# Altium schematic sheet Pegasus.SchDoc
size Tabloid; SheetNumber: 2; SheetTotal: 3
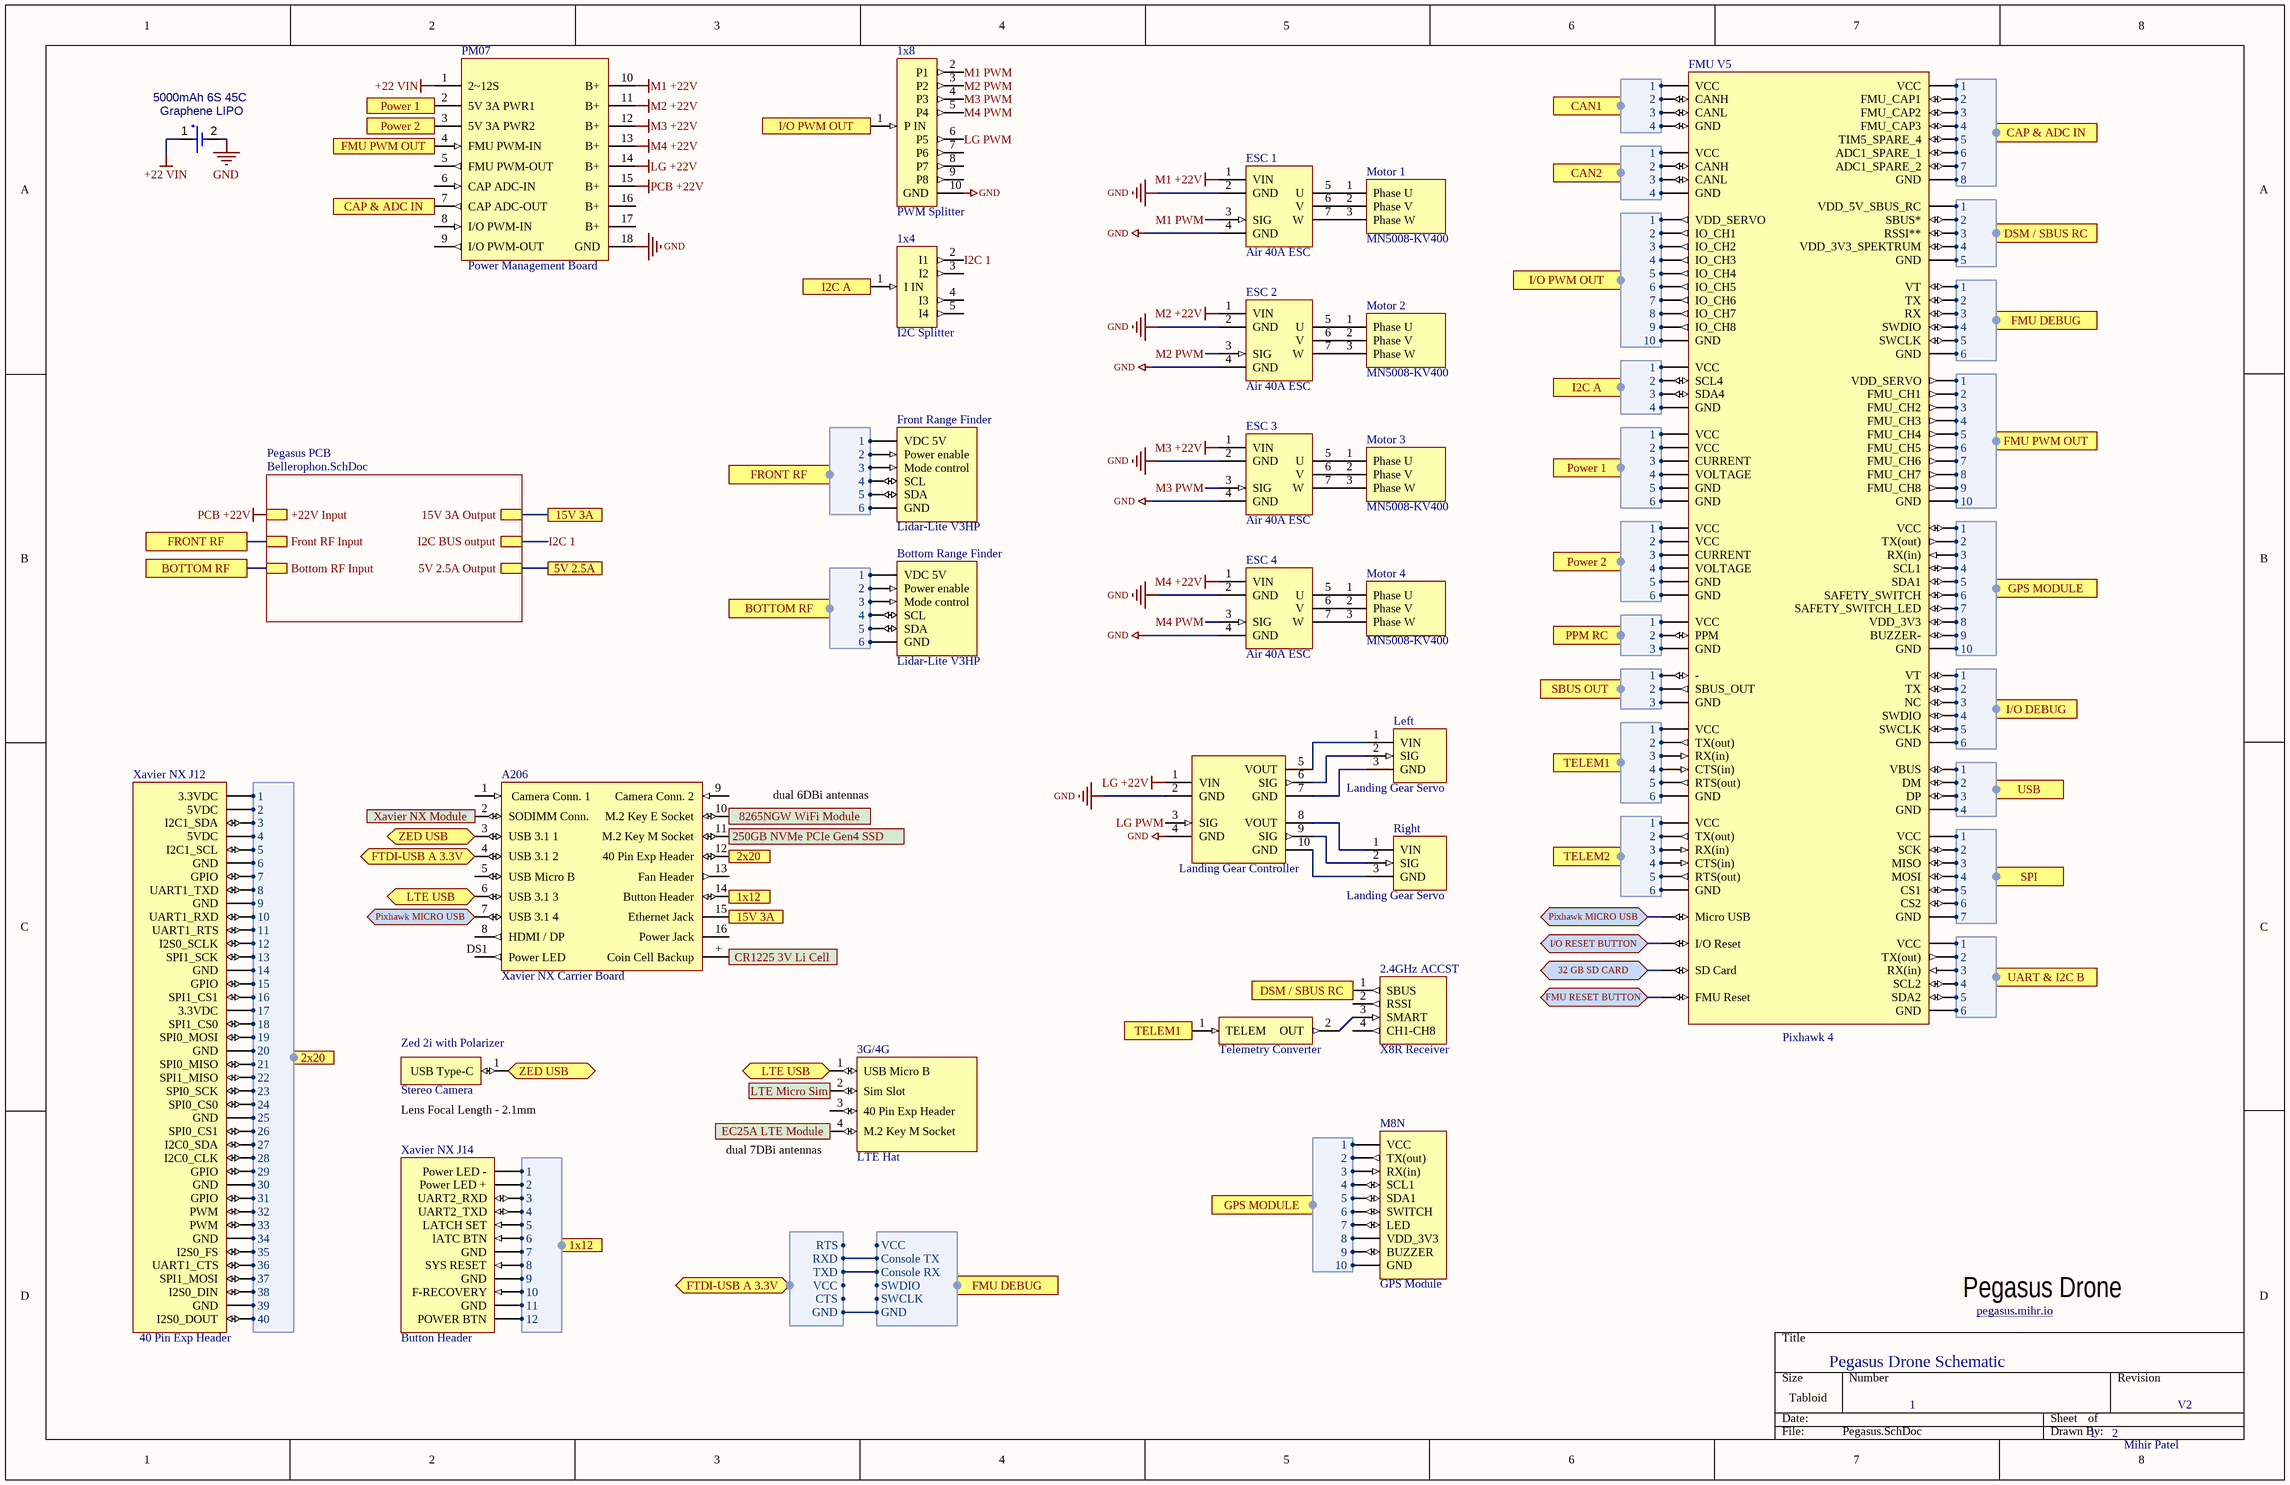
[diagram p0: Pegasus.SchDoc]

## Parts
1x4  I2C Splitter
1x8  PWM Splitter
2.4GHz_ACCST  X8R Receiver
3G/4G  LTE Hat
5000mAh_6S_45C  Graphene LIPO  [SEIK-MS621FE-FL11E-2_V]
A206  Xavier NX Carrier Board
Bottom_Range_Finder  Lidar-Lite V3HP
ESC_1  Air 40A ESC
ESC_2  Air 40A ESC
ESC_3  Air 40A ESC
ESC_4  Air 40A ESC
FMU_V5  Pixhawk 4
Front_Range_Finder  Lidar-Lite V3HP
Left  Landing Gear Servo
LGC  Landing Gear Controller
M8N  GPS Module
Motor_1  MN5008-KV400
Motor_2  MN5008-KV400
Motor_3  MN5008-KV400
Motor_4  MN5008-KV400
PM07  Power Management Board
Right  Landing Gear Servo
TC1  Telemetry Converter
Xavier_NX_J12  40 Pin Exp Header
Xavier_NX_J14  Button Header
Zed_2i_with_Polarizer  Stereo Camera

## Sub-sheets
Pegasus PCB = Bellerophon.SchDoc: 15V 3A Output, +22V Input, Front RF Input, Bottom RF Input, I2C BUS output, 5V 2.5A Output

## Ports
1x12 (harness 1x12), 1x12 (harness *), 2x20 (harness NX), 5V 2.5A, 15V 3A, 32 GB SD CARD (bidir), 250GB NVMe PCIe Gen4 SSD, 8265NGW WiFi Module, BOTTOM RF (harness L2), CAN1 (harness CAN1), CAN2 (harness CAN2), CAP & ADC IN (harness CAP & ADC IN), CR1225 3V Li Cell, DSM / SBUS RC (harness DSM / SBUS RC), EC25A LTE Module, FMU DEBUG (harness FDD), FMU DEBUG (harness FMU DEBUG), FMU PWM OUT (harness FMU PWM OUT), FMU RESET BUTTON (bidir), FRONT RF (harness L1), FTDI-USB A 3.3V (bidir, harness USBD), GPS MODULE (harness GPS MODULE), GPS MODULE (harness GPS), I2C A (harness I2C A), I/O DEBUG (harness IO DEBUG), I/O PWM OUT (harness I/O PWM OUT), I/O RESET BUTTON (bidir), LTE Micro Sim, LTE USB (bidir), Pixhawk MICRO USB (bidir), Power 1 (harness Power 1), Power 2 (harness Power 2), PPM RC (harness PPM RC), SBUS OUT (harness SBUS OUT), SPI (harness SPI), TELEM1 (harness TELEM1), TELEM2 (harness TELEM2), UART & I2C B (harness UART & I2C B), USB (harness USB), Xavier NX Module, ZED USB (bidir)

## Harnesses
CAP & ADC IN: 1, 2, 3, 4, 5, 6, 7, 8
DSM / SBUS RC: 1, 2, 3, 4, 5
FMU DEBUG: 1, 2, 3, 4, 5, 6
FMU PWM OUT: 1, 2, 3, 4, 5, 6, 7, 8, 9, 10
IO DEBUG: 1, 2, 3, 4, 5, 6
SPI: 1, 2, 3, 4, 5, 6, 7
CAN1: 1, 2, 3, 4
CAN2: 1, 2, 3, 4
I/O PWM OUT: 1, 2, 3, 4, 5, 6, 7, 8, 9, 10
I2C A: 1, 2, 3, 4
Power 1: 1, 2, 3, 4, 5, 6
Power 2: 1, 2, 3, 4, 5, 6
SBUS OUT: 1, 2, 3
TELEM1: 1, 2, 3, 4, 5, 6
TELEM2: 1, 2, 3, 4, 5, 6
GPS MODULE: 1, 2, 3, 4, 5, 6, 7, 8, 9, 10
PPM RC: 1, 2, 3
USB: 1, 2, 3, 4
UART & I2C B: 1, 2, 3, 4, 5, 6
L1: 1, 2, 3, 4, 5, 6
L2: 1, 2, 3, 4, 5, 6
GPS: 1, 2, 3, 4, 5, 6, 7, 8, 9, 10
NX: 1, 2, 3, 4, 5, 6, 7, 8, 9, 10, 11, 12, 13, 14, 15, 16, 17, 18, 19, 20, 21, 22, 23, 24, 25, 26, 27, 28, 29, 30, 31, 32, 33, 34, 35, 36, 37, 38, 39, 40
1x12: 1, 2, 3, 4, 5, 6, 7, 8, 9, 10, 11, 12
FDD: VCC, Console TX, Console RX, SWDIO, SWCLK, GND
USBD: GND, CTS, VCC, TXD, RXD, RTS

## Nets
+22 VIN: 5000mAh_6S_45C.1(+) PM07.1(2~12S)
GND: 1x8.10(GND) 5000mAh_6S_45C.2(-) ESC_1.2(GND) ESC_1.4(GND) ESC_2.2(GND) ESC_2.4(GND) ESC_3.2(GND) ESC_3.4(GND) ESC_4.2(GND) ESC_4.4(GND) LGC.2(GND) LGC.4(GND) PM07.18(GND)
LG +22V: LGC.1(VIN) PM07.14(B+)
M1 +22V: ESC_1.1(VIN) PM07.10(B+)
M2 +22V: ESC_2.1(VIN) PM07.11(B+)
M3 +22V: ESC_3.1(VIN) PM07.12(B+)
M4 +22V: ESC_4.1(VIN) PM07.13(B+)
PCB +22V: PM07.15(B+) ; sheet Pegasus PCB/+22V Input
5V 2.5A: port 5V 2.5A, sheet Pegasus PCB/5V 2.5A Output
15V 3A: A206.15(Ethernet_Jack) ; port 15V 3A, sheet Pegasus PCB/15V 3A Output
32 GB SD CARD: FMU_V5.117(SD_Card) ; port 32 GB SD CARD
250GB NVMe PCIe Gen4 SSD: A206.11(M.2_Key_M_Socket) ; port 250GB NVMe PCIe Gen4 SSD
8265NGW WiFi Module: A206.10(M.2_Key_E_Socket) ; port 8265NGW WiFi Module
CR1225 3V Li Cell: A206.+(Coin_Cell_Backup) ; port CR1225 3V Li Cell
EC25A LTE Module: 3G/4G.4(M.2_Key_M_Socket) ; port EC25A LTE Module
FMU RESET BUTTON: FMU_V5.118(FMU_Reset) ; port FMU RESET BUTTON
I2C 1: 1x4.2(I1) ; sheet Pegasus PCB/I2C BUS output
I/O RESET BUTTON: FMU_V5.116(I/O_Reset) ; port I/O RESET BUTTON
LG PWM: 1x8.6(P5) LGC.3(SIG)
LTE Micro Sim: 3G/4G.2(Sim_Slot) ; port LTE Micro Sim
LTE USB: 3G/4G.1(USB_Micro_B) A206.6(USB_3.1_3) ; port LTE USB
M1 PWM: 1x8.2(P1) ESC_1.3(SIG)
M2 PWM: 1x8.3(P2) ESC_2.3(SIG)
M3 PWM: 1x8.4(P3) ESC_3.3(SIG)
M4 PWM: 1x8.5(P4) ESC_4.3(SIG)
Pixhawk MICRO USB: A206.7(USB_3.1_4) FMU_V5.115(Micro_USB) ; port Pixhawk MICRO USB
Xavier NX Module: A206.2(SODIMM_Conn.) ; port Xavier NX Module
ZED USB: A206.3(USB_3.1_1) Zed_2i_with_Polarizer.1(USB_Type-C) ; port ZED USB
Net2.4GHz_ACCST_3: 2.4GHz_ACCST.3(SMART) TC1.2(OUT)
NetBottom_Range_Finder_1: Bottom_Range_Finder.1(VDC_5V) ; port BOTTOM RF.1
NetBottom_Range_Finder_2: Bottom_Range_Finder.2(Power_enable) ; port BOTTOM RF.2
NetBottom_Range_Finder_3: Bottom_Range_Finder.3(Mode_control) ; port BOTTOM RF.3
NetBottom_Range_Finder_4: Bottom_Range_Finder.4(SCL) ; port BOTTOM RF.4
NetBottom_Range_Finder_5: Bottom_Range_Finder.5(SDA) ; port BOTTOM RF.5
NetBottom_Range_Finder_6: Bottom_Range_Finder.6(GND) ; port BOTTOM RF.6
NetESC_1_5: ESC_1.5(U) Motor_1.1(Phase_U)
NetESC_1_6: ESC_1.6(V) Motor_1.2(Phase_V)
NetESC_1_7: ESC_1.7(W) Motor_1.3(Phase_W)
NetESC_2_5: ESC_2.5(U) Motor_2.1(Phase_U)
NetESC_2_6: ESC_2.6(V) Motor_2.2(Phase_V)
NetESC_2_7: ESC_2.7(W) Motor_2.3(Phase_W)
NetESC_3_5: ESC_3.5(U) Motor_3.1(Phase_U)
NetESC_3_6: ESC_3.6(V) Motor_3.2(Phase_V)
NetESC_3_7: ESC_3.7(W) Motor_3.3(Phase_W)
NetESC_4_5: ESC_4.5(U) Motor_4.1(Phase_U)
NetESC_4_6: ESC_4.6(V) Motor_4.2(Phase_V)
NetESC_4_7: ESC_4.7(W) Motor_4.3(Phase_W)
NetFMU_V5_1: FMU_V5.1(VCC) ; port Power 1.1
NetFMU_V5_2: FMU_V5.2(VCC) ; port Power 1.2
NetFMU_V5_3: FMU_V5.3(CURRENT) ; port Power 1.3
NetFMU_V5_4: FMU_V5.4(VOLTAGE) ; port Power 1.4
NetFMU_V5_5: FMU_V5.5(GND) ; port Power 1.5
NetFMU_V5_6: FMU_V5.6(GND) ; port Power 1.6
NetFMU_V5_7: FMU_V5.7(VCC) ; port Power 2.1
NetFMU_V5_8: FMU_V5.8(VCC) ; port Power 2.2
NetFMU_V5_9: FMU_V5.9(CURRENT) ; port Power 2.3
NetFMU_V5_10: FMU_V5.10(VOLTAGE) ; port Power 2.4
NetFMU_V5_11: FMU_V5.11(GND) ; port Power 2.5
NetFMU_V5_12: FMU_V5.12(GND) ; port Power 2.6
NetFMU_V5_13: FMU_V5.13(VCC) ; port TELEM1.1
NetFMU_V5_14: FMU_V5.14(TX(out)) ; port TELEM1.2
NetFMU_V5_15: FMU_V5.15(RX(in)) ; port TELEM1.3
NetFMU_V5_16: FMU_V5.16(CTS(in)) ; port TELEM1.4
NetFMU_V5_17: FMU_V5.17(RTS(out)) ; port TELEM1.5
NetFMU_V5_18: FMU_V5.18(GND) ; port TELEM1.6
NetFMU_V5_19: FMU_V5.19(VBUS) ; port USB.1
NetFMU_V5_20: FMU_V5.20(DM) ; port USB.2
NetFMU_V5_21: FMU_V5.21(DP) ; port USB.3
NetFMU_V5_22: FMU_V5.22(GND) ; port USB.4
NetFMU_V5_23: FMU_V5.23(VCC) ; port TELEM2.1
NetFMU_V5_24: FMU_V5.24(TX(out)) ; port TELEM2.2
NetFMU_V5_25: FMU_V5.25(RX(in)) ; port TELEM2.3
NetFMU_V5_26: FMU_V5.26(CTS(in)) ; port TELEM2.4
NetFMU_V5_27: FMU_V5.27(RTS(out)) ; port TELEM2.5
NetFMU_V5_28: FMU_V5.28(GND) ; port TELEM2.6
NetFMU_V5_29: FMU_V5.29(VCC) ; port CAN1.1
NetFMU_V5_30: FMU_V5.30(CANH) ; port CAN1.2
NetFMU_V5_31: FMU_V5.31(CANL) ; port CAN1.3
NetFMU_V5_32: FMU_V5.32(GND) ; port CAN1.4
NetFMU_V5_33: FMU_V5.33(VCC) ; port I2C A.1
NetFMU_V5_34: FMU_V5.34(SCL4) ; port I2C A.2
NetFMU_V5_35: FMU_V5.35(SDA4) ; port I2C A.3
NetFMU_V5_36: FMU_V5.36(GND) ; port I2C A.4
NetFMU_V5_37: FMU_V5.37(VCC) ; port CAN2.1
NetFMU_V5_38: FMU_V5.38(CANH) ; port CAN2.2
NetFMU_V5_39: FMU_V5.39(CANL) ; port CAN2.3
NetFMU_V5_40: FMU_V5.40(GND) ; port CAN2.4
NetFMU_V5_41: FMU_V5.41(-) ; port SBUS OUT.1
NetFMU_V5_42: FMU_V5.42(SBUS_OUT) ; port SBUS OUT.2
NetFMU_V5_43: FMU_V5.43(GND) ; port SBUS OUT.3
NetFMU_V5_44: FMU_V5.44(VCC) ; port PPM RC.1
NetFMU_V5_45: FMU_V5.45(PPM) ; port PPM RC.2
NetFMU_V5_46: FMU_V5.46(GND) ; port PPM RC.3
NetFMU_V5_47: FMU_V5.47(VDD_SERVO) ; port I/O PWM OUT.1
NetFMU_V5_48: FMU_V5.48(IO_CH1) ; port I/O PWM OUT.2
NetFMU_V5_49: FMU_V5.49(IO_CH2) ; port I/O PWM OUT.3
NetFMU_V5_50: FMU_V5.50(IO_CH3) ; port I/O PWM OUT.4
NetFMU_V5_51: FMU_V5.51(IO_CH4) ; port I/O PWM OUT.5
NetFMU_V5_52: FMU_V5.52(IO_CH5) ; port I/O PWM OUT.6
NetFMU_V5_53: FMU_V5.53(IO_CH6) ; port I/O PWM OUT.7
NetFMU_V5_54: FMU_V5.54(IO_CH7) ; port I/O PWM OUT.8
NetFMU_V5_55: FMU_V5.55(IO_CH8) ; port I/O PWM OUT.9
NetFMU_V5_56: FMU_V5.56(GND) ; port I/O PWM OUT.10
NetFMU_V5_57: FMU_V5.57(VCC) ; port UART & I2C B.1
NetFMU_V5_58: FMU_V5.58(TX(out)) ; port UART & I2C B.2
NetFMU_V5_59: FMU_V5.59(RX(in)) ; port UART & I2C B.3
NetFMU_V5_60: FMU_V5.60(SCL2) ; port UART & I2C B.4
NetFMU_V5_61: FMU_V5.61(SDA2) ; port UART & I2C B.5
NetFMU_V5_62: FMU_V5.62(GND) ; port UART & I2C B.6
NetFMU_V5_63: FMU_V5.63(VDD_5V_SBUS_RC) ; port DSM / SBUS RC.1
NetFMU_V5_64: FMU_V5.64(SBUS*) ; port DSM / SBUS RC.2
NetFMU_V5_65: FMU_V5.65(RSSI**) ; port DSM / SBUS RC.3
NetFMU_V5_66: FMU_V5.66(VDD_3V3_SPEKTRUM) ; port DSM / SBUS RC.4
NetFMU_V5_67: FMU_V5.67(GND) ; port DSM / SBUS RC.5
NetFMU_V5_68: FMU_V5.68(VCC) ; port CAP & ADC IN.1
NetFMU_V5_69: FMU_V5.69(FMU_CAP1) ; port CAP & ADC IN.2
NetFMU_V5_70: FMU_V5.70(FMU_CAP2) ; port CAP & ADC IN.3
NetFMU_V5_71: FMU_V5.71(FMU_CAP3) ; port CAP & ADC IN.4
NetFMU_V5_72: FMU_V5.72(TIM5_SPARE_4) ; port CAP & ADC IN.5
NetFMU_V5_73: FMU_V5.73(ADC1_SPARE_1) ; port CAP & ADC IN.6
NetFMU_V5_74: FMU_V5.74(ADC1_SPARE_2) ; port CAP & ADC IN.7
NetFMU_V5_75: FMU_V5.75(GND) ; port CAP & ADC IN.8
NetFMU_V5_76: FMU_V5.76(VCC) M8N.1(VCC) ; port GPS MODULE.1
NetFMU_V5_77: FMU_V5.77(TX(out)) M8N.2(TX(out)) ; port GPS MODULE.2
NetFMU_V5_78: FMU_V5.78(RX(in)) M8N.3(RX(in)) ; port GPS MODULE.3
NetFMU_V5_79: FMU_V5.79(SCL1) M8N.4(SCL1) ; port GPS MODULE.4
NetFMU_V5_80: FMU_V5.80(SDA1) M8N.5(SDA1) ; port GPS MODULE.5
NetFMU_V5_81: FMU_V5.81(SAFETY_SWITCH) M8N.6(SWITCH) ; port GPS MODULE.6
NetFMU_V5_82: FMU_V5.82(SAFETY_SWITCH_LED) M8N.7(LED) ; port GPS MODULE.7
NetFMU_V5_83: FMU_V5.83(VDD_3V3) M8N.8(VDD_3V3) ; port GPS MODULE.8
NetFMU_V5_84: FMU_V5.84(BUZZER-) M8N.9(BUZZER) ; port GPS MODULE.9
NetFMU_V5_85: FMU_V5.85(GND) M8N.10(GND) ; port GPS MODULE.10
NetFMU_V5_86: FMU_V5.86(VCC) ; port SPI.1
NetFMU_V5_87: FMU_V5.87(SCK) ; port SPI.2
NetFMU_V5_88: FMU_V5.88(MISO) ; port SPI.3
NetFMU_V5_89: FMU_V5.89(MOSI) ; port SPI.4
NetFMU_V5_90: FMU_V5.90(CS1) ; port SPI.5
NetFMU_V5_91: FMU_V5.91(CS2) ; port SPI.6
NetFMU_V5_92: FMU_V5.92(GND) ; port SPI.7
NetFMU_V5_93: FMU_V5.93(VDD_SERVO) ; port FMU PWM OUT.1
NetFMU_V5_94: FMU_V5.94(FMU_CH1) ; port FMU PWM OUT.2
NetFMU_V5_95: FMU_V5.95(FMU_CH2) ; port FMU PWM OUT.3
NetFMU_V5_96: FMU_V5.96(FMU_CH3) ; port FMU PWM OUT.4
NetFMU_V5_97: FMU_V5.97(FMU_CH4) ; port FMU PWM OUT.5
NetFMU_V5_98: FMU_V5.98(FMU_CH5) ; port FMU PWM OUT.6
NetFMU_V5_99: FMU_V5.99(FMU_CH6) ; port FMU PWM OUT.7
NetFMU_V5_100: FMU_V5.100(FMU_CH7) ; port FMU PWM OUT.8
NetFMU_V5_101: FMU_V5.101(FMU_CH8) ; port FMU PWM OUT.9
NetFMU_V5_102: FMU_V5.102(GND) ; port FMU PWM OUT.10
NetFMU_V5_103: FMU_V5.103(VT) ; port FMU DEBUG.1
NetFMU_V5_104: FMU_V5.104(TX) ; port FMU DEBUG.2
NetFMU_V5_105: FMU_V5.105(RX) ; port FMU DEBUG.3
NetFMU_V5_106: FMU_V5.106(SWDIO) ; port FMU DEBUG.4
NetFMU_V5_107: FMU_V5.107(SWCLK) ; port FMU DEBUG.5
NetFMU_V5_108: FMU_V5.108(GND) ; port FMU DEBUG.6
NetFMU_V5_109: FMU_V5.109(VT) ; port I/O DEBUG.1
NetFMU_V5_110: FMU_V5.110(TX) ; port I/O DEBUG.2
NetFMU_V5_111: FMU_V5.111(NC) ; port I/O DEBUG.3
NetFMU_V5_112: FMU_V5.112(SWDIO) ; port I/O DEBUG.4
NetFMU_V5_113: FMU_V5.113(SWCLK) ; port I/O DEBUG.5
NetFMU_V5_114: FMU_V5.114(GND) ; port I/O DEBUG.6
NetFront_Range_Finder_1: Front_Range_Finder.1(VDC_5V) ; port FRONT RF.1
NetFront_Range_Finder_2: Front_Range_Finder.2(Power_enable) ; port FRONT RF.2
NetFront_Range_Finder_3: Front_Range_Finder.3(Mode_control) ; port FRONT RF.3
NetFront_Range_Finder_4: Front_Range_Finder.4(SCL) ; port FRONT RF.4
NetFront_Range_Finder_5: Front_Range_Finder.5(SDA) ; port FRONT RF.5
NetFront_Range_Finder_6: Front_Range_Finder.6(GND) ; port FRONT RF.6
NetLeft_1: Left.1(VIN) LGC.5(VOUT)
NetLeft_2: Left.2(SIG) LGC.6(SIG)
NetLeft_3: Left.3(GND) LGC.7(GND)
NetLGC_8: LGC.8(VOUT) Right.1(VIN)
NetLGC_9: LGC.9(SIG) Right.2(SIG)
NetLGC_10: LGC.10(GND) Right.3(GND)
NetXavier_NX_J12_1: Xavier_NX_J12.1(3.3VDC) ; port 2x20.1
NetXavier_NX_J12_2: Xavier_NX_J12.2(5VDC) ; port 2x20.2
NetXavier_NX_J12_3: Xavier_NX_J12.3(I2C1_SDA) ; port 2x20.3
NetXavier_NX_J12_4: Xavier_NX_J12.4(5VDC) ; port 2x20.4
NetXavier_NX_J12_5: Xavier_NX_J12.5(I2C1_SCL) ; port 2x20.5
NetXavier_NX_J12_6: Xavier_NX_J12.6(GND) ; port 2x20.6
NetXavier_NX_J12_7: Xavier_NX_J12.7(GPIO) ; port 2x20.7
NetXavier_NX_J12_8: Xavier_NX_J12.8(UART1_TXD) ; port 2x20.8
NetXavier_NX_J12_9: Xavier_NX_J12.9(GND) ; port 2x20.9
NetXavier_NX_J12_10: Xavier_NX_J12.10(UART1_RXD) ; port 2x20.10
NetXavier_NX_J12_11: Xavier_NX_J12.11(UART1_RTS) ; port 2x20.11
NetXavier_NX_J12_12: Xavier_NX_J12.12(I2S0_SCLK) ; port 2x20.12
NetXavier_NX_J12_13: Xavier_NX_J12.13(SPI1_SCK) ; port 2x20.13
NetXavier_NX_J12_14: Xavier_NX_J12.14(GND) ; port 2x20.14
NetXavier_NX_J12_15: Xavier_NX_J12.15(GPIO) ; port 2x20.15
NetXavier_NX_J12_16: Xavier_NX_J12.16(SPI1_CS1) ; port 2x20.16
NetXavier_NX_J12_17: Xavier_NX_J12.17(3.3VDC) ; port 2x20.17
NetXavier_NX_J12_18: Xavier_NX_J12.18(SPI1_CS0) ; port 2x20.18
NetXavier_NX_J12_19: Xavier_NX_J12.19(SPI0_MOSI) ; port 2x20.19
NetXavier_NX_J12_20: Xavier_NX_J12.20(GND) ; port 2x20.20
NetXavier_NX_J12_21: Xavier_NX_J12.21(SPI0_MISO) ; port 2x20.21
NetXavier_NX_J12_22: Xavier_NX_J12.22(SPI1_MISO) ; port 2x20.22
NetXavier_NX_J12_23: Xavier_NX_J12.23(SPI0_SCK) ; port 2x20.23
NetXavier_NX_J12_24: Xavier_NX_J12.24(SPI0_CS0) ; port 2x20.24
NetXavier_NX_J12_25: Xavier_NX_J12.25(GND) ; port 2x20.25
NetXavier_NX_J12_26: Xavier_NX_J12.26(SPI0_CS1) ; port 2x20.26
NetXavier_NX_J12_27: Xavier_NX_J12.27(I2C0_SDA) ; port 2x20.27
NetXavier_NX_J12_28: Xavier_NX_J12.28(I2C0_CLK) ; port 2x20.28
NetXavier_NX_J12_29: Xavier_NX_J12.29(GPIO) ; port 2x20.29
NetXavier_NX_J12_30: Xavier_NX_J12.30(GND) ; port 2x20.30
NetXavier_NX_J12_31: Xavier_NX_J12.31(GPIO) ; port 2x20.31
NetXavier_NX_J12_32: Xavier_NX_J12.32(PWM) ; port 2x20.32
NetXavier_NX_J12_33: Xavier_NX_J12.33(PWM) ; port 2x20.33
NetXavier_NX_J12_34: Xavier_NX_J12.34(GND) ; port 2x20.34
NetXavier_NX_J12_35: Xavier_NX_J12.35(I2S0_FS) ; port 2x20.35
NetXavier_NX_J12_36: Xavier_NX_J12.36(UART1_CTS) ; port 2x20.36
NetXavier_NX_J12_37: Xavier_NX_J12.37(SPI1_MOSI) ; port 2x20.37
NetXavier_NX_J12_38: Xavier_NX_J12.38(I2S0_DIN) ; port 2x20.38
NetXavier_NX_J12_39: Xavier_NX_J12.39(GND) ; port 2x20.39
NetXavier_NX_J12_40: Xavier_NX_J12.40(I2S0_DOUT) ; port 2x20.40
NetXavier_NX_J14_1: Xavier_NX_J14.1(Power_LED_-) ; port 1x12.1
NetXavier_NX_J14_2: Xavier_NX_J14.2(Power_LED_+) ; port 1x12.2
NetXavier_NX_J14_3: Xavier_NX_J14.3(UART2_RXD) ; port 1x12.3
NetXavier_NX_J14_4: Xavier_NX_J14.4(UART2_TXD) ; port 1x12.4
NetXavier_NX_J14_5: Xavier_NX_J14.5(LATCH_SET) ; port 1x12.5
NetXavier_NX_J14_6: Xavier_NX_J14.6(lATC_BTN) ; port 1x12.6
NetXavier_NX_J14_7: Xavier_NX_J14.7(GND) ; port 1x12.7
NetXavier_NX_J14_8: Xavier_NX_J14.8(SYS_RESET) ; port 1x12.8
NetXavier_NX_J14_9: Xavier_NX_J14.9(GND) ; port 1x12.9
NetXavier_NX_J14_10: Xavier_NX_J14.10(F-RECOVERY) ; port 1x12.10
NetXavier_NX_J14_11: Xavier_NX_J14.11(GND) ; port 1x12.11
NetXavier_NX_J14_12: Xavier_NX_J14.12(POWER_BTN) ; port 1x12.12
(unnamed): port FMU DEBUG.Console TX, port FTDI-USB A 3.3V.RXD
(unnamed): port FMU DEBUG.Console RX, port FTDI-USB A 3.3V.TXD  [a separate net that carries the same name]
(unnamed): port FMU DEBUG.GND, port FTDI-USB A 3.3V.GND  [a separate net that carries the same name]

Not connected (* = marked no-connect by the designer): 1x4 1(I_IN) 3(I2) 4(I3) 5(I4); 1x8 1(P_IN) 7(P6) 8(P7) 9(P8); 2.4GHz_ACCST 1(SBUS) 2(RSSI) 4(CH1-CH8); 3G/4G 3(40_Pin_Exp_Header); A206 1(_Camera_Conn._1) 4(USB_3.1_2) 5(USB_Micro_B) 8(HDMI_/_DP) 9(Camera_Conn._2) 12(40_Pin_Exp_Header) 13(Fan_Header) 14(Button_Header) 16(Power_Jack) DS1(Power_LED); PM07 2(5V_3A_PWR1) 3(5V_3A_PWR2) 4(FMU_PWM-IN) 5(FMU_PWM-OUT) 6(CAP_ADC-IN) 7(CAP_ADC-OUT) 8(I/O_PWM-IN) 9(I/O_PWM-OUT) 16(B+) 17(B+); TC1 1(TELEM)

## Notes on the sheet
- dual 6DBi antennas
- Lens Focal Length - 2.1mm
- (near 3G/4G) dual 7DBi antennas
- Pegasus Drone
- Pegasus Drone Schematic
- pegasus.mihr.io <http://pegasus.mihr.io>
- 1
- 2
- V2
- Mihir Patel

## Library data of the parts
1x4 = CMP-00028-00024-3: Holybro I2C Splitter
1x8 = CMP-00028-00022-4: Holybro PWM Splitter
2.4GHz_ACCST = CMP-00028-00023-1: FrSky 2.4GHz ACCST
3G/4G = CMP-00028-00027-5: Sixfab LTE Module
5000mAh_6S_45C = CMP-00029-00000-1: MS Lihium Rechargeable Battery, 3 V, -20 to 60 degC, Tray
A206 = CMP-00028-00029-2: A206
Bottom_Range_Finder Front_Range_Finder = CMP-00028-00011-7: Garmin Lidar
ESC_1-ESC_4 = CMP-00028-00016-7: T-Motor ESC 600 Hz
FMU_V5 = CMP-00028-00018-8: FMU V5
Left Right = CMP-00028-00019-3: Tarot 650 Landing Gear Servo Motor
LGC = CMP-00028-00020-2: Tarot 650 LG Controller
M8N = CMP-00028-00021-1: Pixhawk 4 GPS Module
Motor_1-Motor_4 = CMP-00028-00017-4: KV400
PM07 = CMP-00028-00007-5: Holybro Power Module
TC1 = CMP-00028-00026-1: FrSky Yappu Telemetry Converter Cable
Xavier_NX_J12 = CMP-00028-00030-3: Xavier NX Header
Xavier_NX_J14 = CMP-00028-00031-2: Xavier 12 pin J12 Button Header
Zed_2i_with_Polarizer = CMP-00028-00028-2: Zed 2i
